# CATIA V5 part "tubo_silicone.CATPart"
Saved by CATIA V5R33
Part number: tubo_silicone
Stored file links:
  C:\Users\Ryzen5700u\Desktop\robot_cicloidale_singolo\Assieme_robot_cicloidale_singolo\tubo_silicone.CATPart

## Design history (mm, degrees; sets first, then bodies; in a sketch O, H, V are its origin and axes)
Body1 "Solido1" (main body)
  Solid1: solid without history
